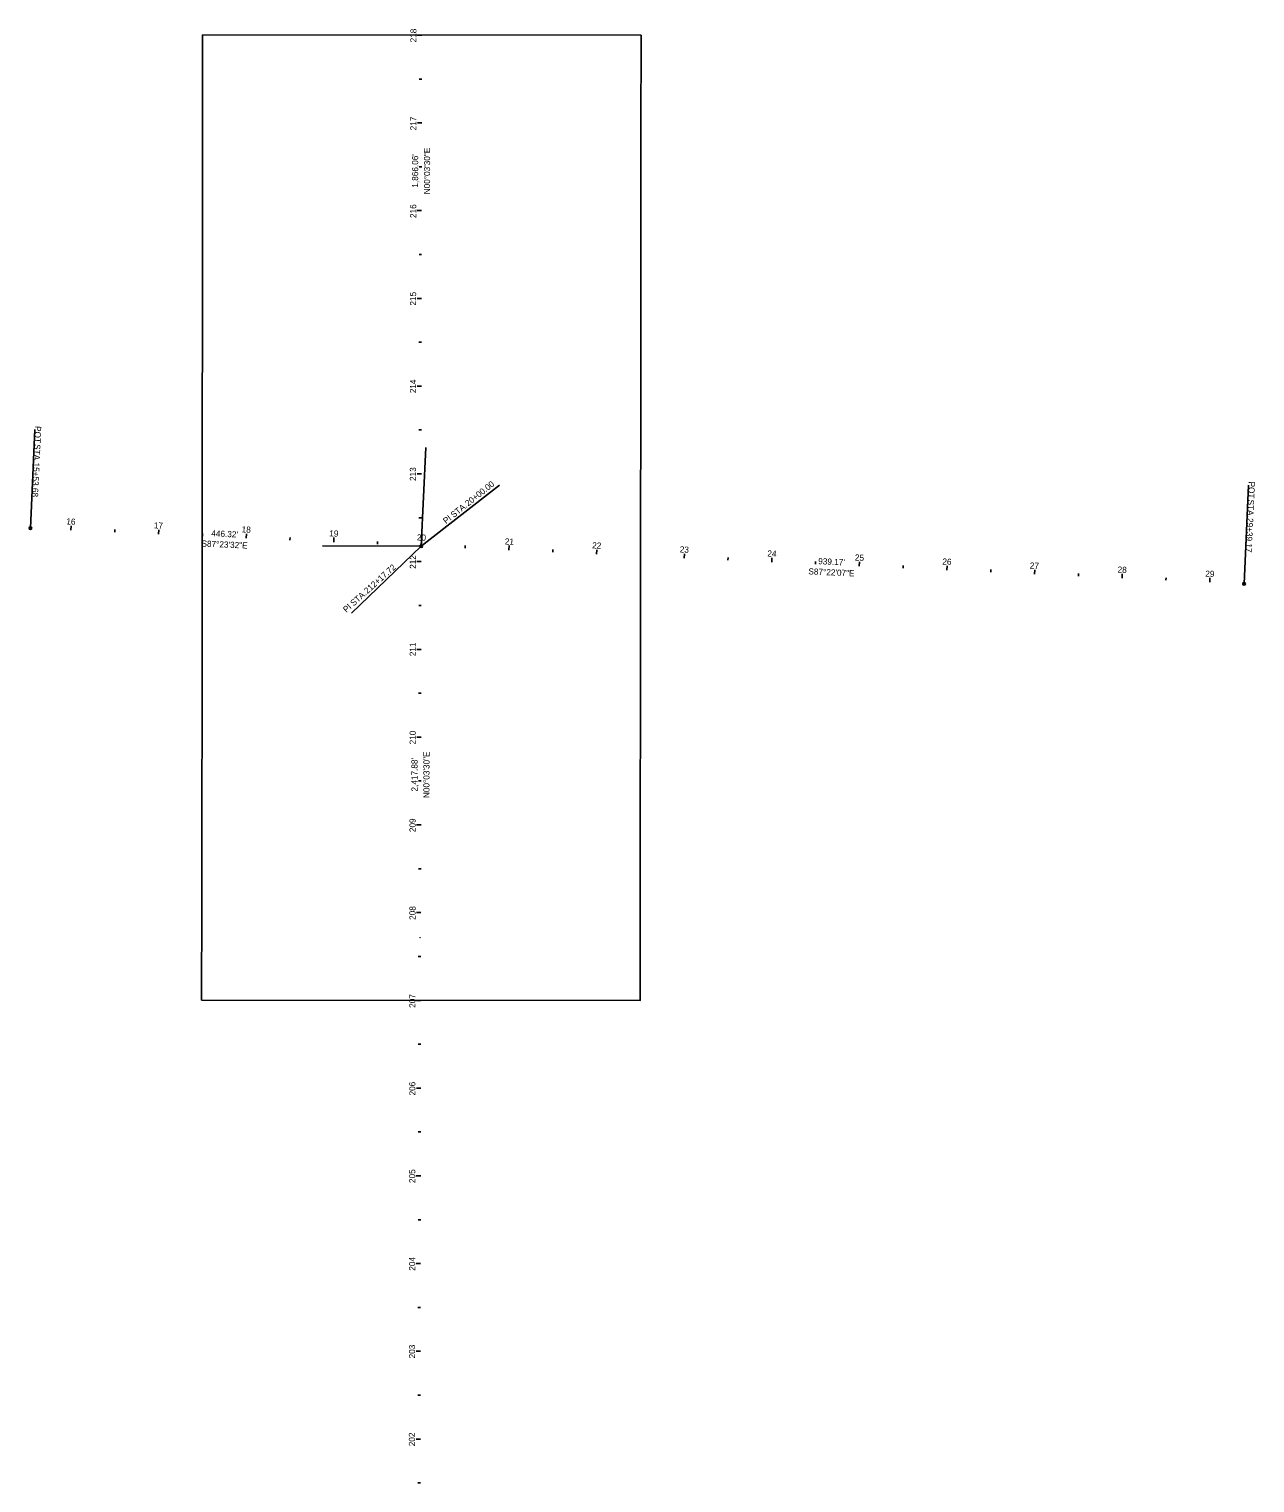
# Model space of a CAD drawing. Extents: x 1805035 to 1810276, y 297762 to 303660.
# Drawn here: x 1808220 to 1809618, y 300719 to 302376 of the extents above; entities that cross this region are included whole.
import ezdxf

# ---------------------------------------------------------------- set-up
doc = ezdxf.new("R2010")
doc.units = 0
for name, color, linetype in [('_CIVIL_CONSTRUCTION', 7, 'Continuous'), ('GE_P_Alignment_100_Bearings', 7, 'Continuous'), ('GE_P_Alignment_100_Cardinal_Points', 7, 'Continuous'), ('GE_P_Alignment_100_Distances', 7, 'Continuous'), ('GE_P_Alignment_100_Stations', 7, 'Continuous'), ('SH_Data', 7, 'Continuous'), ('SH_Named_Boundary', 7, 'Continuous')]:
    doc.layers.add(name, color=color, linetype=linetype)

msp = doc.modelspace()

# ---------------------------------------------------------------- linework, layer by layer
at = {"layer": '_CIVIL_CONSTRUCTION'}
msp.add_circle((1808666.1, 301340.6), 0.05, dxfattribs=at)
at = {"layer": 'GE_P_Alignment_100_Cardinal_Points'}
for p, q in [((1808221.7, 301807.3), (1808226.8, 301919.6)), ((1808667.5, 301786.9), (1808672.7, 301899.3)), ((1809605.7, 301743.8), (1809610.9, 301856.2)), ((1808667.5, 301786.9), (1808555, 301787.1))]:
    msp.add_line(p, q, dxfattribs=at)
for centre in [(1808221.7, 301807.3), (1808667.5, 301786.9), (1808667.5, 301786.9), (1809605.7, 301743.8)]:
    msp.add_circle(centre, 1.5, dxfattribs=at)
at = {"layer": 'GE_P_Alignment_100_Stations'}
for p, q in [((1808668.1, 302369.2), (1808663.1, 302369.2)), ((1808668.1, 302319.2), (1808665.1, 302319.2)), ((1808668, 302269.2), (1808663, 302269.2)), ((1808668, 302219.2), (1808665, 302219.2)), ((1808667.9, 302169.2), (1808662.9, 302169.2)), ((1808667.9, 302119.2), (1808664.9, 302119.2)), ((1808667.8, 302069.2), (1808662.8, 302069.2)), ((1808667.8, 302019.2), (1808664.8, 302019.2)), ((1808667.7, 301969.2), (1808662.7, 301969.2)), ((1808667.7, 301919.2), (1808664.7, 301919.2)), ((1808667.6, 301869.2), (1808662.6, 301869.2)), ((1808667.6, 301819.2), (1808664.6, 301819.2)), ((1808268, 301805.1), (1808268.2, 301810.1)), ((1808317.9, 301802.9), (1808318, 301805.9)), ((1808367.9, 301800.6), (1808368.1, 301805.6)), ((1808417.8, 301798.3), (1808417.9, 301801.3)), ((1808467.7, 301796), (1808468, 301801)), ((1808517.7, 301793.8), (1808517.8, 301796.8)), ((1808567.6, 301791.5), (1808567.9, 301796.5)), ((1808617.6, 301789.2), (1808617.7, 301792.2)), ((1808667.5, 301786.9), (1808667.8, 301791.9)), ((1808717.5, 301784.7), (1808717.6, 301787.7)), ((1808767.4, 301782.4), (1808767.7, 301787.4)), ((1808667.5, 301769.2), (1808662.5, 301769.2)), ((1808817.4, 301780.1), (1808817.5, 301783.1)), ((1808867.3, 301777.8), (1808867.6, 301782.8)), ((1808917.3, 301775.5), (1808917.4, 301778.5)), ((1808967.2, 301773.2), (1808967.5, 301778.2)), ((1809017.2, 301770.9), (1809017.3, 301773.9)), ((1809067.1, 301768.6), (1809067.4, 301773.6)), ((1809117.1, 301766.3), (1809117.2, 301769.3)), ((1809167, 301764), (1809167.2, 301769)), ((1809217, 301761.7), (1809217.1, 301764.7)), ((1809266.9, 301759.4), (1809267.1, 301764.4)), ((1809316.9, 301757.1), (1809317, 301760.1)), ((1809366.8, 301754.8), (1809367, 301759.8)), ((1809416.8, 301752.5), (1809416.9, 301755.5)), ((1809466.7, 301750.2), (1809466.9, 301755.2)), ((1809516.6, 301747.9), (1809516.8, 301750.9)), ((1809566.6, 301745.6), (1809566.8, 301750.6)), ((1808667.5, 301719.2), (1808664.5, 301719.2)), ((1808667.4, 301669.2), (1808662.4, 301669.2)), ((1808667.4, 301619.2), (1808664.4, 301619.2)), ((1808667.3, 301569.2), (1808662.3, 301569.2)), ((1808667.3, 301519.2), (1808664.3, 301519.2)), ((1808667.2, 301469.2), (1808662.2, 301469.2)), ((1808667.2, 301419.2), (1808664.2, 301419.2)), ((1808667.1, 301369.2), (1808662.1, 301369.2)), ((1808667.1, 301319.2), (1808664.1, 301319.2)), ((1808667, 301269.2), (1808662, 301269.2)), ((1808667, 301219.2), (1808664, 301219.2)), ((1808666.9, 301169.2), (1808661.9, 301169.2)), ((1808666.9, 301119.2), (1808663.9, 301119.2)), ((1808666.8, 301069.2), (1808661.8, 301069.2)), ((1808666.8, 301019.2), (1808663.8, 301019.2)), ((1808666.7, 300969.2), (1808661.7, 300969.2)), ((1808666.7, 300919.2), (1808663.7, 300919.2)), ((1808666.6, 300869.2), (1808661.6, 300869.2)), ((1808666.6, 300819.2), (1808663.6, 300819.2)), ((1808666.5, 300769.2), (1808661.5, 300769.2)), ((1808666.5, 300719.2), (1808663.5, 300719.2))]:
    msp.add_line(p, q, dxfattribs=at)
at = {"layer": 'SH_Data'}
for q in [(1808756.8, 301856.5), (1808587.8, 301710.6)]:
    msp.add_line((1808667.5, 301786.9), q, dxfattribs=at)
at = {"layer": 'SH_Named_Boundary'}
msp.add_lwpolyline([(1808417, 301269.5), (1808917, 301269), (1808917.1, 301379), (1808917.2, 301489), (1808917.4, 301599), (1808917.5, 301709), (1808917.6, 301819), (1808917.7, 301929), (1808917.8, 302039), (1808917.9, 302149), (1808918, 302259), (1808918.1, 302369), (1808418.1, 302369.5), (1808418, 302259.5), (1808417.9, 302149.5), (1808417.8, 302039.5), (1808417.7, 301929.5), (1808417.6, 301819.5), (1808417.5, 301709.5), (1808417.4, 301599.5), (1808417.2, 301489.5), (1808417.1, 301379.5)], close=True, dxfattribs=at)

# ---------------------------------------------------------------- texts
at = {"layer": 'GE_P_Alignment_100_Bearings'}
for s, rotation, p in [('N00°03\'30"E', 89.9418, (1808677.5, 302187.8)), ('S87°23\'32"E', 357.3922, (1808416.7, 301786.4)), ('S87°22\'07"E', 357.3686, (1809108.8, 301754.7)), ('N00°03\'30"E', 89.9418, (1808676.8, 301499.7))]:
    msp.add_text(s, height=7, rotation=rotation, dxfattribs=at).set_placement(p)
at = {"layer": 'GE_P_Alignment_100_Cardinal_Points'}
for s, rotation, p in [('POT', 267.3922, (1808227.1, 301923.8)), (' STA. ', 267.3922, (1808226.3, 301905.8)), ('15+53.68', 267.3922, (1808225.2, 301882.2)), ('20+00.00', 38.5061, (1808720.8, 301831.8)), ('POT', 267.3686, (1809611.2, 301860.6)), (' STA. ', 267.3686, (1809610.4, 301842.6)), ('PI', 38.5061, (1808695.7, 301811.8)), (' STA. ', 38.5061, (1808702.3, 301817.1)), ('29+39.17', 267.3686, (1809609.3, 301819)), ('212+17.72', 41.7874, (1808606, 301732.1)), ('PI', 41.7874, (1808582, 301710.7)), (' STA. ', 41.7874, (1808588.4, 301716.3))]:
    msp.add_text(s, height=7, rotation=rotation, dxfattribs=at).set_placement(p)
at = {"layer": 'GE_P_Alignment_100_Distances'}
for s, rotation, p in [("1,866.06'", 89.9418, (1808663.9, 302195.4)), ("446.32'", 357.3922, (1808427.9, 301798)), ("939.17'", 357.3686, (1809120, 301766.3)), ("2,417.88'", 89.9418, (1808663.2, 301507.2))]:
    msp.add_text(s, height=7, rotation=rotation, dxfattribs=at).set_placement(p)
at = {"layer": 'GE_P_Alignment_100_Stations'}
for s, rotation, p in [('218', 89.9418, (1808661.9, 302360.9)), ('217', 89.9418, (1808661.8, 302260.7)), ('216', 89.9418, (1808661.7, 302160.8)), ('215', 89.9418, (1808661.6, 302061)), ('214', 89.9418, (1808661.5, 301961.1)), ('213', 89.9418, (1808661.4, 301861.1)), ('16', 357.3922, (1808262.6, 301811.6)), ('17', 357.3922, (1808362.4, 301807.1)), ('18', 357.3922, (1808462.5, 301802.5)), ('19', 357.3922, (1808562.4, 301798)), ('20', 357.3922, (1808662.3, 301793.4)), ('21', 357.3686, (1808762.6, 301788.8)), ('22', 357.3686, (1808862.2, 301784.3)), ('23', 357.3686, (1808962.1, 301779.7)), ('212', 89.9418, (1808661.3, 301761)), ('24', 357.3686, (1809062, 301775.1)), ('25', 357.3686, (1809161.8, 301770.5)), ('26', 357.3686, (1809261.6, 301765.9)), ('27', 357.3686, (1809361.3, 301761.3)), ('28', 357.3686, (1809461.4, 301756.7)), ('29', 357.3686, (1809561.4, 301752.1)), ('211', 89.9418, (1808661.2, 301661.4)), ('210', 89.9418, (1808661.1, 301560.9)), ('209', 89.9418, (1808661, 301460.9)), ('208', 89.9418, (1808660.9, 301360.9)), ('207', 89.9418, (1808660.8, 301260.7)), ('206', 89.9418, (1808660.7, 301160.8)), ('205', 89.9418, (1808660.6, 301061)), ('204', 89.9418, (1808660.5, 300961.1)), ('203', 89.9418, (1808660.4, 300861.1)), ('202', 89.9418, (1808660.3, 300761))]:
    msp.add_text(s, height=7, rotation=rotation, dxfattribs=at).set_placement(p)

doc.saveas('drawing.dxf')
